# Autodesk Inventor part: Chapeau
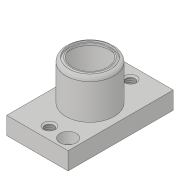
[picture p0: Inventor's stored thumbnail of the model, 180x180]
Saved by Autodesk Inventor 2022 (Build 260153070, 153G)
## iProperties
Created: 2018-06
Part Number: Chapeau
Material: Aluminium 6061
Document SubType Name: Modeling
Designer: Fabian Perrée
Density: 2.7 g/cm^3
Appearance: Générique
Mass: 26.5554 g
Surface Area: 66.9581 cm^2
Volume: 9.83534 cm^3
Author: Fabian Perrée
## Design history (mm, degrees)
sketch "Esquisse1"
  geometry: L1 (-14, 24)-(14, 24); L2 (14, 24)-(14, -24); L3 (14, -24)-(-14, -24); L4 (-14, -24)-(-14, 24); L5 (-14, 24)-(14, -24); L6 (14, 24)-(-14, -24); 1 further point
  constraints: 12 end point, 2 midpoint, 2 parallel, 1 horizontal, 1 perpendicular
  dimensions: "d0" = 28 distance of L2.end L3.end; "d1" = 48 distance of L1.end L2.end
extrude "Extrusion1" new body sketch "Esquisse1" distance "d2" = 8; taper "d3" = 0 deg
sketch "Esquisse2"
  geometry: L1 (0, 0)-(8, 0); L2 (8, -24)-(8, 24) reference; L3 (26, -11)-(26, -9.5); L4 (26, -9.5)-(25, -9.5); L5 (25, -9.5)-(26, -8.5); L6 (26, -8)-(24.268, -9); L7 (24.268, -9)-(8, -9); L8 (8, -9)-(8, -11); L9 (26, -11)-(8, -11); L10 (26, -8.5)-(26, -8); L11 (8, -9)-(2.5, -9); L12 (2.5, -9)-(2.5, -11.5); L13 (2.5, -11.5)-(0, -11.5); L14 (0, 24)-(0, -24) reference; L15 (0, -11.5)-(0, 0); L16 (8, -9)-(8, 0); L17 (8, 0)-(26, 0)
  constraints: 30 end point, 5 point on line, 4 horizontal, 4 perpendicular, 2 collinear, 2 vertical, 1 midpoint
  dimensions: "d4" = 18 distance from line of L2 L17.end; "d5" = 1.5 distance of L3.start L3.end; "d6" = 1 distance of L3.end L4.end; "d7" = 45 deg angle of L4 L5; "d8" = 150 deg angle of L7 L6; "d9" = 22 diameter of L9 L1; "d10" = 16 diameter of L6.start L1; "d11" = 18 diameter of L7 L1; "d12" = 23 diameter of L13 L1; "d13" = 18 diameter of L11 L1; "d14" = 2.5 distance of L12.end L13.end
revolve "Révolution1" stored, may be unused: angle "d15" = 90 deg
revolve "Révolution2" stored, may be unused: angle "d16" = 90 deg
sketch "Esquisse3"
  geometry: L1 (14, -24)-(14, 24) reference; L2 (-14, -24)-(14, -24) reference; L3 (-14, 24)-(-14, -24) reference; L4 (14, 24)-(-14, 24) reference; 3 further points
  dimensions: "d17" = 5 distance from line of L1 point (9, -19); "d18" = 5 distance from line of L2 point (9, -19); "d19" = 5 distance from line of L3 point (-9, 19); "d20" = 5 distance from line of L4 point (-9, 19)
hole "Perçage1" sketch "Esquisse3" at (-9, 19), (9, -19) diameter "d21" = 4.5; stored, may be unused: countersink angle "d25" = 90 deg, drill point angle "d27" = 118 deg; dims "d22" = 6, "d23" = 7.5, "d24" = 5, "d26" = 8
sketch "Esquisse4"
  geometry: L1 (-14, 24)-(-14, -24) reference; L2 (-14, -24)-(14, -24) reference; L3 (14, 24)-(-14, 24) reference; 4 further points
  constraints: 2 vertical alignment, 1 midpoint
  dimensions: "d29" = 5.5 distance from line of L2 point (0, -18.5) (= d31); "d31" = 5.5 distance from line of L3 point (0, 18.5)
hole "Perçage2" sketch "Esquisse4" at (0, -18.5), (0, 18.5) diameter "d32" = 4.134; stored, may be unused: countersink angle "d36" = 90 deg, drill point angle "d38" = 118 deg; dims "d33" = 10, "d34" = 5.5, "d35" = 5, "d37" = 14.2
fillet "Congé1" dims "d51" = 2
feature "Scission1"
node "Solide1"
